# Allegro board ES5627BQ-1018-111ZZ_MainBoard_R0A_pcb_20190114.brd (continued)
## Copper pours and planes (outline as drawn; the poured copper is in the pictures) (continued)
XFP_3V3-R_P18 on BOTTOM (solid shape): 151.2,64.07 151.16,63.99 150.52,63.81 150.27,63.28 150.27,63.06 149.49,63.06 149.17,63.38 149.17,64.66 149.21,64.72 149.87,64.72 149.87,65.53 149.87,66.81 149.36,67.32 149.36,68.59 149.42,68.65 151.2,68.65
XFP_3V3-R_P19 on TOP (solid shape): 166.86,68.3 166.86,67.68 166.02,66.84 166.02,65.53 165.98,65.53 165.98,64.72 166.02,64.72 166.02,63.26 165.84,63.09 164.45,63.09 164.32,63.22 164.32,68.3 164.45,68.42 166.73,68.42
XFP_3V3-R_P20 on BOTTOM (solid shape): 163.71,63.44 163.65,63.38 163.65,63.13 163.58,63.06 163.38,63.06 163.38,63.42 163.06,63.75 162.34,63.82 162.12,63.13 162.12,63.12 162.12,63.06 161.99,63.06 161.68,63.38 161.68,64.66 161.72,64.71 162.38,64.71 162.38,65.53 162.38,66.81 161.87,67.32 161.87,68.59 161.93,68.65 163.71,68.65
XFP_3V3-R_P21 on TOP (solid shape): 179.5,68.3 179.5,67.53 178.76,66.8 178.73,66.8 178.73,65.98 178.73,65.98 178.73,65.53 178.64,65.53 178.64,64.71 178.73,64.71 178.73,63.34 178.48,63.09 177.08,63.09 176.96,63.22 176.96,68.3 177.08,68.42 179.37,68.42
XFP_3V3-R_P22 on BOTTOM (solid shape): 176.35,63.94 176.31,63.86 176.22,63.84 175.95,63.83 175.71,63.69 175.09,63.06 174.63,63.06 174.31,63.38 174.31,64.71 175.01,64.71 175.01,65.53 175.01,66.81 174.5,67.32 174.5,68.59 174.57,68.65 176.35,68.65
XFP_3V3-R_P23 on TOP (solid shape): 192.13,68.3 192.13,67.62 192.08,67.54 192.04,67.45 192.04,67.44 191.4,66.8 191.37,66.8 191.37,65.98 191.37,65.53 191.28,65.53 191.28,64.71 191.37,64.71 191.37,63.34 191.12,63.09 189.72,63.09 189.59,63.22 189.59,68.3 189.72,68.42 192,68.42
XFP_3V3-R_P24 on BOTTOM (solid shape): 188.98,63.91 188.94,63.83 188.85,63.82 188.22,63.73 187.92,63.16 187.89,63.09 187.82,63.06 187.27,63.06 186.95,63.38 186.95,64.55 187.08,64.68 187.54,64.68 187.58,64.71 187.65,64.71 187.65,65.53 187.65,65.53 187.65,66.81 187.14,67.32 187.14,68.55 187.24,68.55 187.3,68.62 187.36,68.62 187.4,68.65 188.98,68.65
XFP_3V3-T_P01 on TOP (solid shape): 31.52,68.3 31.52,63.22 31.39,63.09 29.74,63.09 29.49,63.34 29.49,64.61 29.59,64.71 30.21,64.71 30.21,64.74 30.25,64.74 30.25,66.77 29.67,67.35 29.69,67.39 29.75,67.64 29.69,67.89 29.69,68.2 29.62,68.28 29.62,68.3 29.74,68.42 31.39,68.42
XFP_3V3-T_P02 on BOTTOM (solid shape): 34.67,68.52 34.66,68.49 34.64,68.39 34.63,68.29 34.63,67.6 34.63,67.55 34.64,67.48 33.96,66.8 33.93,66.8 33.93,65.98 33.96,65.98 34.24,65.7 34.26,65.59 34.17,65.53 33.84,65.53 33.84,64.71 34.45,64.71 34.45,64.12 34.67,63.9 34.74,63.84 34.82,63.79 34.82,63.22 34.7,63.09 34.02,63.09 33.94,63.13 33.92,63.22 33.66,63.86 32.97,63.77 32.66,63.47 32.54,63.6 32.54,68.5 32.69,68.65 34.54,68.65
XFP_3V3-T_P03 on TOP (solid shape): 44.03,68.3 44.03,63.22 43.9,63.09 42.25,63.09 42,63.34 42,64.18 42,64.18 42.02,64.33 42,64.49 42,64.62 42.04,64.66 42.79,64.66 42.79,65.47 42.76,65.47 42.76,66.77 42.12,67.41 42.12,68.3 42.25,68.42 43.9,68.42
XFP_3V3-T_P04 on BOTTOM (solid shape): 47.18,68.52 47.17,68.49 47.15,68.39 47.14,68.29 47.14,67.6 47.14,67.55 47.15,67.48 46.47,66.8 46.44,66.8 46.44,65.98 46.47,65.98 46.75,65.7 46.77,65.59 46.68,65.53 46.35,65.53 46.35,64.71 46.96,64.71 46.96,64.12 47.18,63.9 47.25,63.84 47.33,63.79 47.33,63.22 47.2,63.09 45.67,63.09 45.62,63.14 45.62,63.35 45.45,63.75 45.05,63.92 45.05,68.5 45.2,68.65 47.05,68.65
XFP_3V3-T_P05 on TOP (solid shape): 56.6,68.3 56.6,63.22 56.48,63.09 54.82,63.09 54.57,63.34 54.57,64.59 54.58,64.59 54.58,64.62 54.68,64.72 55.36,64.72 55.36,65.53 55.33,65.53 55.33,66.77 54.72,67.39 54.7,67.46 54.7,68.3 54.82,68.42 56.48,68.42
XFP_3V3-T_P06 on BOTTOM (solid shape): 59.75,68.52 59.75,68.49 59.72,68.39 59.71,68.29 59.71,67.47 59.04,66.8 59.02,66.8 59.02,65.98 59.04,65.98 59.32,65.7 59.35,65.59 59.25,65.53 58.93,65.53 58.93,64.71 59.53,64.71 59.53,64.12 59.75,63.9 59.83,63.84 59.9,63.79 59.9,63.22 59.78,63.09 58.43,63.09 58.04,63.48 58.03,63.49 57.89,63.73 57.65,63.88 57.62,63.89 57.62,68.5 57.77,68.65 59.63,68.65
XFP_3V3-T_P07 on TOP (solid shape): 69.11,68.3 69.11,63.22 68.99,63.09 67.33,63.09 67.08,63.34 67.08,63.98 67.13,64.03 67.13,64.59 67.15,64.59 67.15,64.68 67.19,64.72 67.93,64.72 67.93,65.53 67.84,65.53 67.84,66.77 67.21,67.41 67.21,68.3 67.33,68.42 68.99,68.42
XFP_3V3-T_P08 on BOTTOM (solid shape): 72.26,68.52 72.25,68.49 72.23,68.39 72.22,68.29 72.22,67.6 72.22,67.55 72.23,67.48 71.55,66.8 71.52,66.8 71.52,65.98 71.55,65.98 71.83,65.7 71.86,65.59 71.76,65.53 71.44,65.53 71.44,64.71 72.04,64.71 72.04,64.12 72.26,63.9 72.33,63.84 72.41,63.79 72.41,63.22 72.29,63.09 70.92,63.09 70.85,63.12 70.47,63.5 70.47,63.51 70.34,63.69 70.16,63.81 70.13,63.82 70.13,68.5 70.28,68.65 72.13,68.65
XFP_3V3-T_P09 on TOP (solid shape): 81.62,68.58 81.62,63.22 81.49,63.09 79.84,63.09 79.59,63.34 79.59,64.61 79.69,64.71 80.31,64.71 80.31,64.74 80.35,64.74 80.35,66.77 79.72,67.41 79.72,68.51 79.84,68.64 81.56,68.64
XFP_3V3-T_P10 on BOTTOM (solid shape): 84.48,68.54 84.48,67.48 84.03,67.03 84.03,67.02 83.91,66.89 83.91,65.6 83.87,65.55 83.87,64.71 83.97,64.61 84.49,64.61 84.49,64.19 84.77,63.9 84.84,63.84 84.92,63.79 84.92,63.22 84.8,63.09 83.64,63.09 82.98,63.75 82.84,63.85 82.68,63.91 82.64,63.92 82.64,68.5 82.79,68.65 84.37,68.65
XFP_3V3-T_P11 on TOP (solid shape): 112.44,68.3 112.44,63.22 112.31,63.09 110.66,63.09 110.41,63.34 110.41,64.61 110.51,64.71 111.13,64.71 111.13,64.74 111.17,64.74 111.17,66.77 110.53,67.41 110.53,68.3 110.66,68.42 112.31,68.42
XFP_3V3-T_P12 on BOTTOM (solid shape): 115.59,68.52 115.58,68.49 115.56,68.39 115.55,68.29 115.55,68.15 115.44,68.03 115.29,67.81 115.23,67.54 115.23,67.5 115.25,67.35 115.29,67.21 114.88,66.8 114.85,66.8 114.85,65.97 114.8,65.92 114.8,65.53 114.76,65.53 114.76,64.71 115.37,64.71 115.37,64.12 115.59,63.9 115.66,63.84 115.74,63.79 115.74,63.22 115.62,63.09 115.59,63.09 114.09,63.09 114.09,63.26 113.92,63.71 113.5,63.95 113.46,63.95 113.46,68.5 113.61,68.65 115.46,68.65
XFP_3V3-T_P13 on TOP (solid shape): 125.01,68.3 125.01,63.22 124.89,63.09 123.23,63.09 122.98,63.34 122.98,64.61 123.08,64.71 123.7,64.71 123.7,64.74 123.74,64.74 123.74,66.77 123.11,67.41 123.11,68.3 123.23,68.42 124.89,68.42
XFP_3V3-T_P14 on BOTTOM (solid shape): 128.16,68.52 128.15,68.49 128.13,68.39 128.12,68.29 128.12,67.6 128.12,67.55 128.13,67.48 127.45,66.8 127.42,66.8 127.42,65.98 127.45,65.98 127.73,65.7 127.76,65.59 127.66,65.53 127.34,65.53 127.34,65.41 127.33,65.4 127.33,64.77 127.34,64.77 127.34,64.71 127.39,64.71 127.4,64.71 127.94,64.71 127.94,64.12 128.16,63.9 128.23,63.84 128.31,63.79 128.31,63.22 128.19,63.09 126.58,63.09 126.58,63.35 126.44,63.77 126.07,64.02 126.03,64.03 126.03,68.5 126.18,68.65 128.03,68.65
XFP_3V3-T_P15 on TOP (solid shape): 133.15,68.17 133.15,63.09 133.02,62.97 131.37,62.97 131.12,63.22 131.12,64.49 131.22,64.59 131.84,64.59 131.84,64.62 131.88,64.62 131.88,65.26 131.99,65.37 131.99,66.78 131.42,67.35 131.42,68.3 133.02,68.3
XFP_3V3-T_P16 on BOTTOM (solid shape): 136.3,68.4 136.29,68.37 136.27,68.27 136.26,68.16 136.26,67.48 136.26,67.43 136.27,67.36 135.59,66.68 135.56,66.68 135.56,65.86 135.59,65.86 135.87,65.58 135.89,65.47 135.8,65.41 135.47,65.41 135.47,64.59 136.08,64.59 136.08,64 136.3,63.78 136.37,63.72 136.45,63.67 136.45,63.09 136.33,62.97 135.02,62.97 134.39,63.6 134.3,63.67 134.2,63.72 134.17,63.73 134.17,68.38 134.32,68.53 136.17,68.53
XFP_3V3-T_P17 on TOP (solid shape): 151.17,68.3 151.17,63.22 151.05,63.09 149.4,63.09 149.14,63.34 149.14,64.61 149.25,64.72 149.87,64.72 149.87,64.74 149.9,64.74 149.9,66.77 149.27,67.41 149.27,68.3 149.4,68.42 151.05,68.42
XFP_3V3-T_P18 on BOTTOM (solid shape): 154.33,68.52 154.32,68.49 154.29,68.24 154.35,67.99 154.35,67.53 153.61,66.8 153.59,66.8 153.59,66.77 153.51,66.69 153.51,65.53 153.5,65.53 153.5,64.71 153.51,64.71 153.51,64.68 153.69,64.49 154.1,64.49 154.1,64.12 154.32,63.9 154.4,63.84 154.48,63.79 154.48,63.22 154.35,63.09 153.42,63.09 152.61,63.9 152.43,64.03 152.23,64.1 152.19,64.1 152.19,68.5 152.34,68.65 154.2,68.65
XFP_3V3-T_P19 on TOP (solid shape): 163.68,68.3 163.68,63.22 163.56,63.09 161.91,63.09 161.65,63.34 161.65,64.61 161.76,64.72 162.38,64.72 162.38,64.74 162.41,64.74 162.41,66.77 161.78,67.41 161.78,68.3 161.91,68.42 163.56,68.42
XFP_3V3-T_P20 on BOTTOM (solid shape): 166.84,68.52 166.83,68.49 166.8,68.39 166.79,68.29 166.79,67.73 166.02,66.95 166.02,65.89 166.2,65.7 166.22,65.59 166.13,65.53 165.98,65.53 165.98,64.72 166.53,64.72 166.53,64.12 166.79,63.86 166.88,63.78 166.99,63.72 166.99,63.22 166.86,63.09 165.21,63.09 165.13,63.17 165.13,63.35 165.02,63.68 164.73,63.89 164.7,63.9 164.7,68.5 164.85,68.65 166.71,68.65
XFP_3V3-T_P21 on TOP (solid shape): 176.32,68.3 176.32,63.22 176.19,63.09 174.54,63.09 174.29,63.34 174.29,64.61 174.39,64.71 175.01,64.71 175.01,64.74 175.05,64.74 175.05,66.77 174.42,67.41 174.42,68.3 174.54,68.42 176.19,68.42
XFP_3V3-T_P22 on BOTTOM (solid shape): 179.47,68.52 179.46,68.49 179.44,68.39 179.43,68.29 179.43,67.47 178.76,66.8 178.73,66.8 178.73,65.98 178.76,65.98 179.04,65.7 179.06,65.59 178.97,65.53 178.64,65.53 178.64,64.71 179.25,64.71 179.25,64.12 179.47,63.9 179.54,63.84 179.62,63.79 179.62,63.22 179.5,63.09 178.2,63.09 177.6,63.69 177.49,63.77 177.37,63.83 177.34,63.84 177.34,68.5 177.49,68.65 179.34,68.65
XFP_3V3-T_P23 on TOP (solid shape): 188.96,68.3 188.96,63.22 188.95,63.21 188.95,62.91 188.75,62.71 187.56,62.71 186.92,63.34 186.92,64.61 187.03,64.71 187.65,64.71 187.65,64.74 187.69,64.74 187.69,66.77 187.05,67.41 187.05,68.3 187.18,68.42 188.83,68.42
XFP_3V3-T_P24 on BOTTOM (solid shape): 192.11,68.52 192.1,68.49 192.08,68.39 192.07,68.29 192.07,67.79 191.9,67.55 191.85,67.27 191.85,67.25 191.4,66.8 191.37,66.8 191.37,65.98 191.4,65.98 191.68,65.7 191.7,65.59 191.61,65.53 191.28,65.53 191.28,64.71 191.89,64.71 191.89,64.12 192.11,63.9 192.18,63.84 192.26,63.79 192.26,63.22 192.13,63.09 191.2,63.09 191.07,63.19 190.92,63.25 190.91,63.26 190.32,63.84 190.18,63.95 190.01,64.02 189.97,64.03 189.97,68.5 190.13,68.65 191.98,68.65
XFP_3V3_12V_VIN on TOP: 173.5,106.7 169.44,106.7 169.31,106.83 169.31,107.59 169.19,107.72 163.47,107.72 162.46,106.7 158.01,106.7 157.88,106.83 157.88,107.46 156.79,108.56 156.79,109.14 156.89,109.24 157.5,109.24 157.55,109.29 157.55,109.93 158.01,110.39 166.52,110.39 166.65,110.51 172.23,110.51 172.36,110.39 172.36,109.37 172.49,109.24 173.5,109.24 173.63,109.12 173.63,106.83
XFP_3V3_12V_VIN on BOTTOM: 157.96,110.36 171.27,110.36 171.95,109.67 171.95,106.98 171.68,106.7 157.71,106.7 157.17,107.24 157.17,109.57
XFP_3V3_GND on TOP: 147.22,90.45 147.09,90.57 147.09,92.1 147.34,92.35 147.72,92.35 148.1,92.73 149.12,92.73 149.25,92.61 149.25,89.31 149.04,89.1 148,89.1 147.22,89.88
XFP_3V3_GND on TOP: 143.59,102.55 143.59,101.3 143.61,101.3 143.88,101.03 145.44,101.03 145.75,101.34 145.75,102.7 145.62,102.83 143.87,102.83
XFP_3V3_GND on S7: 143.91,100.15 143.66,100.4 143.66,101.62 143.82,101.79 145.4,101.79 147.98,99.21 147.98,96.29 148.3,95.97 148.3,93.88 148.99,93.18 148.99,91.74 149.64,91.1 150.53,91.1 151.22,91.8 151.22,93.21 150.53,93.9 150.53,95.84 151.03,96.34 152.75,96.34 153.44,95.65 153.44,91.59 150.7,88.85 145.18,88.85 143.91,90.11
XFP_3V3_P01_02 on TOP (solid shape): 35.71,73.12 35.71,69.69 35.61,69.59 34.92,69.59 34.92,69.06 32.02,69.06 31.66,69.06 29.49,69.06 29.36,69.18 29.36,69.44 29.26,69.54 29.26,69.72 28.6,69.72 28.6,70.33 28.92,70.65 28.94,70.65 29.15,70.71 29.31,70.84 32.03,70.84 32.28,71.09 32.28,73.25 32.54,73.5 35.33,73.5
XFP_3V3_P01_02 on BOTTOM (solid shape): 35.71,72.84 35.71,69.85 35.51,69.64 35.1,69.64 35.05,69.59 34.92,69.59 34.92,69.36 34.85,69.29 32.43,69.29 29.69,69.29 29.59,69.39 29.59,69.46 29.49,69.57 29.26,69.57 29.26,69.72 28.6,69.72 28.6,70.33 28.92,70.65 28.94,70.65 29.15,70.71 29.31,70.84 32.03,70.84 32.28,71.09 32.28,72.11 33.43,73.25 35.3,73.25
XFP_3V3_P03_04 on TOP (solid shape): 48.22,73.12 48.22,69.69 48.12,69.59 47.43,69.59 47.43,69.06 44.53,69.06 44.17,69.06 42,69.06 41.87,69.18 41.87,69.44 41.77,69.54 41.77,69.72 41.11,69.72 41.11,70.33 41.5,70.72 41.52,70.73 41.66,70.76 41.78,70.84 42.79,70.84 43.21,70.62 43.64,70.84 46.03,70.84 46.25,71.06 46.25,73.36 46.4,73.5 47.84,73.5
XFP_3V3_P03_04 on BOTTOM (solid shape): 48.22,72.84 48.22,69.85 48.02,69.64 47.61,69.64 47.56,69.59 47.43,69.59 47.43,69.36 47.36,69.29 47.29,69.29 44.94,69.29 44.93,69.29 42.2,69.29 42.1,69.39 42.1,69.46 42,69.57 41.77,69.57 41.77,69.72 41.11,69.72 41.11,70.33 41.5,70.72 41.52,70.73 41.66,70.76 41.78,70.84 42.79,70.84 43.21,70.62 43.64,70.84 44.54,70.84 44.79,71.09 44.79,72.11 45.93,73.25 47.81,73.25
XFP_3V3_P05_06 on TOP (solid shape): 60.79,73.12 60.79,69.69 60.69,69.59 60.01,69.59 60.01,69.06 57.1,69.06 56.74,69.06 54.57,69.06 54.44,69.18 54.44,69.44 54.34,69.54 54.34,69.72 53.68,69.72 53.68,70.33 54.19,70.84 55.15,70.84 55.24,70.75 55.68,70.75 56.05,70.66 56.38,70.84 57.11,70.84 57.11,70.84 58.49,70.84 58.82,71.17 58.82,73.36 58.96,73.5 60.41,73.5
XFP_3V3_P05_06 on BOTTOM (solid shape): 61.18,72.46 61.18,70.23 60.59,69.64 60.18,69.64 60.13,69.59 60.01,69.59 60.01,69.36 59.93,69.29 57.51,69.29 54.77,69.29 54.67,69.39 54.67,69.46 54.57,69.57 54.34,69.57 54.34,69.72 53.68,69.72 53.68,70.33 54.19,70.84 55.58,70.84 55.98,70.66 56.38,70.84 57.11,70.84 57.36,71.09 57.36,72.11 58.51,73.25 60.39,73.25
XFP_3V3_P07_08 on TOP (solid shape): 73.3,73.12 73.3,69.69 73.2,69.59 72.52,69.59 72.52,69.06 69.61,69.06 69.25,69.06 67.08,69.06 66.95,69.18 66.95,69.44 66.85,69.54 66.85,69.72 66.19,69.72 66.19,70.33 66.39,70.53 66.43,70.51 66.64,70.43 66.87,70.44 66.88,70.45 67.02,70.45 67.41,70.84 67.57,70.84 67.97,70.44 68.09,70.44 68.1,70.43 68.51,70.48 68.77,70.8 68.78,70.84 70.86,70.84 71.28,71.25 71.28,73.38 71.4,73.5 72.92,73.5
XFP_3V3_P07_08 on BOTTOM (solid shape): 73.3,72.84 73.3,69.85 73.1,69.64 72.69,69.64 72.64,69.59 72.52,69.59 72.52,69.36 72.44,69.29 70.02,69.29 67.28,69.29 67.18,69.39 67.18,69.46 67.08,69.57 66.85,69.57 66.85,69.72 66.19,69.72 66.19,70.33 66.39,70.53 66.43,70.51 66.9,70.45 67.23,70.8 67.24,70.84 67.73,70.84 67.74,70.8 68.25,70.41 68.77,70.8 68.78,70.84 69.62,70.84 69.87,71.09 69.87,72.11 71.02,73.25 72.9,73.25
XFP_3V3_P09_10 on TOP (solid shape): 85.33,72.52 85.33,72.46 85.34,72.33 85.32,72.33 85.32,70.38 85.54,70.38 85.54,70.09 85.61,70.03 85.6,70 85.61,69.85 85.66,69.71 85.65,69.61 85.56,69.57 85.12,69.57 85.08,69.53 85.03,69.53 85.03,69.06 84.93,69.06 84.73,69.26 84.7,69.26 84.68,69.28 82.25,69.28 82.23,69.26 81.84,69.26 81.82,69.27 79.63,69.27 79.46,69.44 79.46,69.57 79.4,69.63 79.36,69.63 79.36,69.72 78.7,69.72 78.7,70.33 78.85,70.47 82.91,70.47 83.32,70.89 83.32,73 83.82,73.5 85.33,73.5
XFP_3V3_P09_10 on BOTTOM (solid shape): 85.31,73 85.31,72.21 85.68,71.84 85.56,71.72 85.56,69.95 85.59,69.77 85.67,69.61 85.7,69.58 85.65,69.53 85.03,69.53 85.03,69.37 84.95,69.29 84.64,69.29 82.53,69.29 82.53,69.29 79.79,69.29 79.79,69.58 79.68,69.7 79.36,69.7 79.36,69.72 78.74,69.72 78.7,69.75 78.7,70.33 79.02,70.65 79.84,70.65 80.03,70.84 80.35,70.84 80.83,70.54 81.31,70.84 82.13,70.84 82.38,71.09 82.38,72.11 83.53,73.25 85.06,73.25
XFP_3V3_P11_12 on TOP (solid shape): 116.63,73.12 116.63,69.69 116.54,69.6 115.96,69.6 115.95,69.59 115.84,69.59 115.84,69.09 115.81,69.06 112.94,69.06 112.58,69.06 110.41,69.06 110.31,69.15 110.31,69.7 110.24,69.76 109.61,69.76 109.52,69.86 109.52,70.33 109.91,70.72 109.93,70.73 110.05,70.75 110.16,70.81 110.68,70.81 110.71,70.84 112.95,70.84 113.2,71.09 113.2,73.25 113.46,73.5 116.25,73.5
XFP_3V3_P11_12 on BOTTOM (solid shape): 116.63,72.84 116.63,69.85 116.43,69.64 116.02,69.64 115.97,69.59 115.84,69.59 115.84,69.36 115.77,69.29 113.34,69.29 110.61,69.29 110.51,69.39 110.51,69.46 110.25,69.73 109.63,69.73 109.52,69.84 109.52,70.33 109.91,70.72 109.93,70.73 110.07,70.76 110.19,70.84 112.95,70.84 113.2,71.09 113.2,72.11 114.34,73.25 116.22,73.25
XFP_3V3_P13_14 on TOP (solid shape): 129.2,73.12 129.2,69.69 129.13,69.62 128.42,69.62 128.36,69.57 128.36,69.12 128.3,69.06 125.51,69.06 122.98,69.06 122.9,69.14 122.9,69.5 122.77,69.63 122.75,69.63 122.75,69.72 122.09,69.72 122.09,70.33 122.49,70.72 122.5,70.73 122.62,70.75 122.73,70.81 123.25,70.81 123.28,70.84 125.52,70.84 125.77,71.09 125.77,73.25 126.03,73.5 128.82,73.5
XFP_3V3_P13_14 on BOTTOM (solid shape): 129.2,72.84 129.2,69.85 129,69.64 128.59,69.64 128.54,69.59 128.42,69.59 128.42,69.36 128.34,69.29 128.28,69.29 125.92,69.29 125.92,69.29 123.18,69.29 123.16,69.31 123.16,69.5 122.96,69.7 122.75,69.7 122.75,69.72 122.13,69.72 122.09,69.76 122.09,70.66 122.2,70.77 122.23,70.76 122.51,70.73 122.76,70.84 125.52,70.84 125.77,71.09 125.77,72.11 126.92,73.25 128.8,73.25
XFP_3V3_P15_16 on TOP (solid shape): 137.34,73 137.34,69.57 137.3,69.52 136.57,69.52 136.49,69.44 136.49,69.06 136.36,68.94 131.12,68.94 130.99,69.06 130.99,69.47 130.86,69.6 130.23,69.6 130.23,70.21 130.5,70.48 134.16,70.48 135.03,71.35 135.03,73 135.41,73.38 136.96,73.38
XFP_3V3_P15_16 on BOTTOM (solid shape): 137.34,72.72 137.34,69.72 137.14,69.52 136.73,69.52 136.68,69.47 136.55,69.47 136.55,69.24 136.48,69.16 134.06,69.16 131.54,69.16 131.07,69.63 130.29,69.63 130.23,69.7 130.23,70.21 130.74,70.71 132,70.71 132.37,70.56 132.74,70.71 133.66,70.71 133.91,70.97 133.91,71.98 135.06,73.13 136.93,73.13
XFP_3V3_P17_18 on TOP (solid shape): 155.37,73.12 155.37,69.69 155.26,69.59 154.58,69.59 154.58,69.57 154.5,69.57 154.5,69.06 151.67,69.06 149.14,69.06 149.02,69.18 149.02,69.44 148.91,69.54 148.91,69.72 148.25,69.72 148.25,70.33 148.76,70.84 151.68,70.84 151.94,71.09 151.94,73.25 152.19,73.5 154.98,73.5
XFP_3V3_P17_18 on BOTTOM (solid shape): 155.37,72.84 155.37,69.85 155.16,69.64 154.76,69.64 154.71,69.59 154.58,69.59 154.58,69.36 154.5,69.29 154.44,69.29 152.08,69.29 152.08,69.29 149.35,69.29 149.24,69.39 149.24,69.46 149.14,69.57 148.91,69.57 148.91,69.72 148.25,69.72 148.25,70.33 148.76,70.84 151.68,70.84 151.94,71.09 151.94,72.11 153.08,73.25 154.96,73.25
XFP_3V3_P19_20 on TOP (solid shape): 167.87,73.12 167.87,69.69 167.77,69.59 167.09,69.59 167.09,69.06 166.99,69.06 164.18,69.06 163.82,69.06 161.65,69.06 161.52,69.18 161.52,69.44 161.42,69.54 161.42,69.72 161.24,69.72 161.24,69.73 160.76,69.73 160.76,70.33 161.27,70.84 164.19,70.84 164.45,71.09 164.45,73.25 164.7,73.5 167.49,73.5
XFP_3V3_P19_20 on BOTTOM (solid shape): 167.87,72.84 167.87,69.85 167.67,69.64 167.27,69.64 167.21,69.59 167.09,69.59 167.09,69.36 167.01,69.29 164.59,69.29 161.85,69.29 161.75,69.39 161.75,69.46 161.65,69.57 161.42,69.57 161.42,69.72 160.76,69.72 160.76,70.33 161.27,70.84 164.19,70.84 164.45,71.09 164.45,72.11 165.59,73.25 167.47,73.25
XFP_3V3_P21_22 on TOP (solid shape): 180.51,73.12 180.51,69.69 180.41,69.59 179.72,69.59 179.72,69.57 179.71,69.57 179.71,69.06 176.82,69.06 174.29,69.06 174.16,69.18 174.16,69.44 174.06,69.54 174.06,69.72 173.88,69.72 173.88,69.72 173.4,69.72 173.4,70.33 173.91,70.84 176.83,70.84 177.08,71.09 177.08,73.25 177.34,73.5 180.13,73.5
XFP_3V3_P21_22 on BOTTOM (solid shape): 180.51,72.84 180.51,69.85 180.31,69.64 179.9,69.64 179.85,69.59 179.72,69.59 179.72,69.36 179.65,69.29 179.58,69.29 177.23,69.29 177.22,69.29 174.49,69.29 174.46,69.31 174.21,69.31 174.06,69.46 174.06,69.72 173.42,69.72 173.4,69.74 173.4,70.33 173.91,70.84 176.83,70.84 177.08,71.09 177.08,72.11 178.23,73.25 180.1,73.25
XFP_3V3_P23_24 on TOP (solid shape): 193.15,73.12 193.15,69.69 193.08,69.62 192.49,69.62 192.46,69.59 192.36,69.59 192.36,69.06 189.46,69.06 189.09,69.06 186.92,69.06 186.8,69.18 186.8,69.44 186.7,69.54 186.7,69.72 186.04,69.72 186.04,70.33 186.52,70.81 187.2,70.81 187.22,70.84 189.46,70.84 189.72,71.09 189.72,72.82 190.4,73.5 192.77,73.5
XFP_3V3_P23_24 on BOTTOM (solid shape): 193.15,72.84 193.15,69.85 192.94,69.64 192.54,69.64 192.49,69.59 192.36,69.59 192.36,69.36 192.28,69.29 189.86,69.29 187.14,69.29 187.1,69.25 187.04,69.25 186.97,69.19 186.85,69.19 186.72,69.31 186.72,69.63 186.7,69.65 186.7,69.72 186.08,69.72 186.04,69.76 186.04,70.33 186.54,70.84 189.46,70.84 189.72,71.09 189.72,72.95 190.02,73.25 192.74,73.25
XFP_3V3_PCL_SW on TOP (solid shape): 157.75,103.15 162.46,103.15 162.72,103.4 163.72,103.4 163.84,103.27 163.95,103.27 163.95,103.12 165.28,103.12 165.28,103.15 165.48,103.15 165.48,103.12 166.8,103.12 166.8,103.15 167.91,103.15 168.05,103.28 168.49,103.32 171.82,103.32 172.22,102.92 172.22,98.08 171.83,97.69 158.14,97.69 157.76,98.07 157.76,98.84 157.89,99.36 157.5,99.73 157.49,99.73 157.15,100.07 157.15,100.38 156.84,100.38 156.61,100.61 156.61,103.27 156.74,103.4 157.49,103.4
N61195405 on TOP: 204.57,252.81 204.57,247.22 205.16,246.63 209.04,246.63 209.27,246.41 214.2,246.41 214.25,246.46 214.25,247.04 214.1,247.19 210.49,247.19 209.58,248.11 209.58,252.78 208.74,253.62 205.38,253.62
N61307888 on G2 (solid shape): outline of 1081 points within 250.38,12.67 265.97,70.94
N61307888 on V3 (solid shape): outline of 1081 points within 250.38,12.67 265.97,70.94
N61307888 on G4 (solid shape): outline of 1081 points within 250.38,12.67 265.97,70.94
N61307888 on G6 (solid shape): outline of 1081 points within 250.38,12.67 265.97,70.94
N61307888 on G8 (solid shape): outline of 1081 points within 250.38,12.67 265.97,70.94
N61307888 on G10 (solid shape): outline of 1081 points within 250.38,12.67 265.97,70.94
N61307888 on G11 (solid shape): outline of 1081 points within 250.38,12.67 265.97,70.94
N61307888 on G13 (solid shape): outline of 1081 points within 250.38,12.67 265.97,70.94
N61307888 on G15 (solid shape): outline of 1081 points within 250.38,12.67 265.97,70.94
N61307888 on G17 (solid shape): outline of 1081 points within 250.38,12.67 265.97,70.94
N61307888 on G19 (solid shape): outline of 1115 points within 250.38,12.67 265.97,70.94
N61983825 on G2 (solid shape): outline of 1159 points within 220.44,12.8 240.41,80.36
N61983825 on G4 (solid shape): outline of 1159 points within 220.44,12.8 240.41,80.36
N61983825 on G6 (solid shape): outline of 1159 points within 220.44,12.8 240.41,80.36
N61983825 on G8 (solid shape): outline of 1160 points within 220.44,12.8 240.43,80.36
N61983825 on G10 (solid shape): outline of 1160 points within 220.44,12.8 240.43,80.36
N61983825 on G11 (solid shape): outline of 1160 points within 220.44,12.8 240.43,80.36
N61983825 on G13 (solid shape): outline of 1160 points within 220.44,12.8 240.43,80.36
N61983825 on G15 (solid shape): outline of 1160 points within 220.44,12.8 240.43,80.36
N61983825 on G17 (solid shape): outline of 1170 points within 220.44,12.8 240.43,80.36
N61983825 on G19 (solid shape): outline of 1201 points within 220.44,12.8 240.43,80.36

Small or netless copper shapes (teardrops, artwork), in the pictures only: 44 on TOP, 1 on BOTTOM, 1 on V3, 2 on S5, 2 on S7, 1 on S9, 1 on S12, 1 on S14, 2 on S16, 1 on G10, 2 on V18

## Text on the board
Ref Des/Silkscreen Bottom: A | B | G | W
User.Comments: CR_CONN_POWER_1 | CR_UNNAMED_1 | CR_UNNAMED_25 | CR_1_9 | CR_CONN_POWER_2 | CR_UNNAMED_2 | CR_UNNAMED_26 | CR_0_2 | CR_1_10 | CR_CONN_POWER_3 | CR_UNNAMED_27 | CR_1_11 | CR_UNNAMED_3 | CR_2_3 | CR_0_4 | CR_UNNAMED_28 | CR_CONN_POWER_4 | CR_UNNAMED_4 | CR_1_13 | CR_2_1 | CR_CONN_POWER_5 | CR_UNNAMED_29 | CR_1_14 | CR_2_2 | CR_UNNAMED_30 | CR_CONN_POWER_10 | CR_2_4 | CR_CONN_POWER_9 | CR_UNNAMED_6 | CR_UNNAMED_7 | CR_1_15 | CR_UNNAMED_8 | CR_1_16 | CR_2_5 | CR_CONN_POWER_7 | CR_UNNAMED_9 | CR_1_17 | CR_2_6 | CR_CONN_POWER_8 | CR_UNNAMED_10 | CR_U160_3 | CR_CONN18_1 | CR_CONN18_2 | CR_U160_6 | CR_U25_1 | CR_U25_2 | CR_2_7 | CR_1_18 | CR_CONN_POWER_11 | CR_UNNAMED_11 | CR_UNNAMED_34 | CR_2_8 | CR_CONN_POWER_12 | CR_1_19 | CR_UNNAMED_35 | CR_UNNAMED_12 | CR_2_9 | CR_1_20 | CR_CONN_POWER_13 | CR_UNNAMED_36 | CR_UNNAMED_13 | CR_2_10 | CR_CONN_POWER_14 | CR_UNNAMED_37 | CR_1_21 | CR_UNNAMED_14 | CR_2_11 | CR_CONN_POWER_15 | CR_UNNAMED_38 | CR_UNNAMED_15 | CR_2_12 | CR_CONN_POWER_16 | CR_UNNAMED_39 | CR_UNNAMED_16 | CR_2_13 | CR_UNNAMED_40 | CR_CONN_POWER_17 | CR_UNNAMED_17 | CR_2_14 | CR_UNNAMED_41 | CR_CONN_POWER_18 | CR_UNNAMED_18 | CR_2_15 | CR_UNNAMED_42 | CR_CONN_POWER_19 | CR_UNNAMED_19 | CR_2_16 | CR_CONN_POWER_20 | CR_UNNAMED_20
Ref Des/Assembly Top: 37 | 36 | 35 | 34 | 33 | 32 | 31 | 30 | 29 | P/N:142000002193H REV.0A
Ref Des/Silkscreen Top: RR | U | K | P | D | T | WW | B | C | Q | PO | UU | EE | A | 0 | O
User.10: ∅4.2 [∅0.165] | {\Fromans,stsl|c134;4-∅4.5 [∅0.177]}
User.11: TOP (COMPONENT_SIDE)                       1
User.12: G2 (GND_LAYER_2)                           2
User.13: S5 (SIGNAL_LAYER_5)                           5
User.14: BOT (SOLDER_SIDE)                         20
User.15: SST (SILKSCREEN_TOP)                      21
User.16: SSB (SILKSCREEN_BOTTOM)                   22
User.17: SMT (SOLDER_MASK_TOP)                     23
User.18: SMB (SOLDER_MASK_BOTTOM)                  24
User.19: DRILL(FINISH HOLE SIZE LIST)                  27 | First drill hole + secind drill hole=8 | Visible drill hole=4 | Drill size=177 mil
User.20: PMT (PASTE_MASK_TOP)                     25
User.21: PMB (PASTE_MASK_BOTTOM)                  26
User.22: DIM (BOARD_DIMENSION)                    34
User.24: G4 (GND_LAYER_4 )                         4
User.25: G6 (GND_LAYER_6)                           6
User.26: S7 (SIGNAL_LAYER_7)                           7
User.27: G8 (VCC_LAYER_8)                           8
User.30: G11 (GND_LAYER_11)                         11
User.31: S12 (SIGNAL_LAYER_12)                         12
User.32: G13 (GND_LAYER_13)                         13
User.33: G15 (GND_LAYER_15)                         15
User.34: S14 (SIGNAL_LAYER_14)                         14
User.35: G17 (GND_LAYER_17)                         17
User.36: S16 (SIGNAL_LAYER_16)                         16
User.37: BACKDRILL(DRILL-BD-20-17)                  33 | NO MUST CUT LAYER:S16 | MUST CUT LAYER:G17
User.38: BACKDRILL(DRILL-BD-20-15)                   28 | NO MUST CUT LAYER:S14 | MUST CUT LAYER:G15
User.39: BACKDRILL(DRILL-BD-20-13)                   32 | NO MUST CUT LAYER:S12 | MUST CUT LAYER:G13
User.40: BACKDRILL(DRILL-BD-20-10)                  30 | NO MUST CUT LAYER:S9 | MUST CUT LAYER:G10
User.41: BACKDRILL(DRILL-BD-20-6)                     28 | NO MUST CUT LAYER:S5 | MUST CUT LAYER:G6
User.42: BACKDRILL(DRILL-BD-20-8)                     29 | NO MUST CUT LAYER:S7 | MUST CUT LAYER:G8
User.43: V18 (VCC_LAYER_18)                    18
User.44: V3 (VCC_LAYER_3)                          3
User.45: 9 | 8 | 7 | 3 | 2 | 1 | H | F | D | B | T | P | M | K | N | J | G | C | A | R | L | E | RB134 | RB135 | CB322 | RB1210 | CB922 | R1195 | R1044 | R1054 | R1045 | R1039 | CB1078 | CB321 | RB1200 | LEDB6 | CB323 | CB1076 | RB184 | CB1030 | TP50 | LEDB5 | RB186 | CB1015 | CB1066 | CB1064 | CB1005 | CB1004 | CB1003 | CB1016 | CB996 | CB1072 | CB1070 | RB1199 | CB1006 | CB1033 | CB1013 | CB1001 | CB1007 | CB1008 | CB1058 | CB1036 | CB1022 | CB1024 | R1116 | R1098 | RB1212 | RB256 | R1100 | R1082 | TP51 | RB1215 | RB1206 | RB1208 | R1084 | R1086 | RB760 | RB1209 | LEDB4 | CB1088 | RB325 | RB1213 | CB440 | LEDB3 | UB71 | CB942 | CB950 | CB953 | CB954 | RB324 | FB3 | CB329 | RB662 | RB669 | RB678 | RB688 | RB273 | RB278 | RB280 | RB283 | R1237 | RB1217 | RB766 | CB896 | R332 | CB736 | CB1041 | CB1044 | UB10 | RB1216 | CB710 | RB223 | CB895 | CB1080 | CB737 | R1236 | UB70 | CB1083 | CB1085 | CB1079 | CB1082 | RB1201 | RB639 | CB755 | R1110 | CB894 | C538 | CB1040 | CB1042 | RB1221 | RB1219 | CB795 | TPB54 | RB155 | RB748 | CB730 | CB687 | CB711 | RB638 | CB939 | CB893 | CB794 | CB668 | TPB55 | RB750 | CB383 | CB584 | CB1039 | R1115 | R1114 | R1096 | R1097 | R1102 | R1103 | CB1043 | CB1073 | CB940 | RB203 | RB747 | R182 | R1081 | CB1054 | RB1211 | CB1037 | CB1050 | CB785 | LB72 | RB452 | RB488 | RB524 | RB560 | RB762 | RB763 | RB451 | RB487 | RB523 | RB201 | RB188 | RB561 | RB489 | RB152 | RB161 | RB525 | RB164 | RB166 | RB170 | RB453 | RB211 | CB522 | RB225 | RB217 | RB151 | CB351 | RB160 | RB163 | RB230 | RB165 | RB169 | CB881 | UB7 | RB216 | RB224 | RB226 | RB229 | RB231 | RB234 | CB849 | QB4 | DB6 | QB6 | R1228 | UB11 | CB880 | RB559 | CB848 | R1170 | R1171 | LB2 | CB11 | RB149 | CB349 | FB7 | RB558 | CB105 | DB3 | RB157 | CB97 | RB765 | RB557 | CB879 | CB847 | RB556 | CB934 | LB3 | CB878 | CB846 | RB555 | CB14 | CB925 | CB147 | CB1093 | RB450 | RB486 | RB522 | CB845 | UB2 | CB146 | CB877 | DB4 | RB554 | RB449 | RB485 | RB521 | CB844 | CB200 | CB178 | CB876 | CB96 | CB103 | RB448 | RB484 | RB520 | FB6 | QB5 | CB843 | RB553 | LB5 | QB7 | LB6 | RB44 | CB29 | CB875 | RB447 | RB483 | RB519 | RB576 | CB935 | CB225 | CB842 | RB446 | RB482 | RB518 | CB72 | CB400 | CB417 | CB240 | CB874 | RB575 | RB215 | RB445 | RB481 | RB517 | DB5 | CB109 | CB121 | CB129 | CB841 | RB574 | RB181 | RB504 | RB540 | RB468 | RB159 | RB538 | CB101 | CB873 | RB503 | RB467 | RB539 | RB189 | CB170 | RB502 | RB466 | CB108 | CB128 | CB840 | CB872 | RB4 | CB509 | RB465 | RB501 | RB537 | RB573 | UB14 | CB793 | CB239 | CB224 | RB572 | RB536 | RB500 | RB464 | QB2 | CB21 | CB839 | CB871 | RB109 | RB659 | RB571 | RB535 | RB123 | LB85 | RB499 | LB16 | RB463 | CB219 | CB245 | CB952 | CB272 | CB252 | RB97 | CB959 | RB686 | CB256 | CB194 | CB184 | CB171 | CB223 | CB237 | RB462 | CB870 | LB81 | LB79 | RB498 | RB570 | RB534 | RB87 | RB652 | RB93 | RB685 | RB569 | RB533 | RB497 | RB461 | CB958 | CB938 | RB496 | RB532 | RB568 | LB26 | RB183 | CB123 | RB460 | LB80 | CB545 | RB582 | CB330 | CB334 | CB328 | RB664 | RB673 | RB552 | RB516 | CB594 | CB837 | RB599 | RB608 | RB616 | RB629 | RB637 | CB869 | CB137 | CB158 | CB169 | CB179 | CB188 | CB207 | CB222 | CB238 | CB259 | RB444 | RB480 | RB581 | RB591 | RB648 | RB658 | RB663 | RB672 | DB7 | CB456 | CB570 | UB3 | CB89 | CB733 | LB11 | RB443 | RB479 | RB515 | RB551 | RB689 | RB697 | RB708 | RB714 | CB759 | RB727 | CB868 | CB836 | LB15 | RB442 | RB478 | RB550 | RB514 | CB215 | CB189 | CB500 | RB679 | RB703 | CB835 | CB867 | C447 | RB590 | RB647 | RB8 | RB657 | RB607 | RB628 | RB228 | CB973 | RB721 | CB985 | RB744 | RB513 | RB615 | RB598 | RB636 | CB283 | CB102 | CB111 | CB834 | CB866 | RB441 | RB549 | RB440 | RB476 | RB512 | RB548 | RB477 | CB163 | CB264 | CB151 | CB126 | CB949 | RB743 | RB746 | CB757 | SWB2 | CB654 | CB404 | RB176 | CB833 | LB22 | CB865 | UB12 | CB211 | RB218 | CB120 | RB742 | RB745 | RB89 | RB94 | RB439 | RB475 | RB511 | RB547 | RB546 | RB438 | RB474 | RB510 | UB17 | RB666 | CB205 | RB683 | CB686 | RB702 | RB614 | RB580 | RB589 | RB597 | RB38 | RB22 | RB635 | CB550 | CB290 | CB413 | CB366 | RB606 | RB627 | RB646 | RB707 | SWB1 | CB618 | CB832 | CB5 | RB5 | RB37 | RB21 | CB864 | RB694 | RB656 | RB677 | CB313 | RB47 | CB90 | CB212 | RB713 | CB32 | UB1 | RB46 | TPB47 | RB173 | RB712 | RB720 | CB315 | RB437 | RB473 | RB509 | RB545 | RB596 | RB676 | RB706 | CB9 | RB626 | RB655 | RB701 | RB588 | RB579 | RB645 | RB605 | RB613 | RB634 | CB696 | RB436 | RB472 | RB508 | RB544 | RB682 | RB693 | CB975 | RB665 | RB578 | RB654 | UB16 | OSCB1 | CB314 | RB595 | RB603 | RB612 | RB633 | RB435 | RB471 | RB507 | RB543 | RB731 | RB625 | RB644 | RB587 | CB279 | CB292 | CB236 | RB99 | RB85 | RB90 | RB40 | RB7 | CB110 | RB110 | RB116 | RB102 | RB730 | RB741 | CB857 | CB34 | RB6 | RB39 | CB210 | LB53 | CB287 | CB299 | RB13 | RB29 | CB863 | CB136 | RB729 | RB740 | RB96 | CB801 | TPB48 | RB92 | RB28 | RB12 | RB100 | RB107 | CB783 | LEDB10 | RB632 | RB611 | RB594 | RB728 | RB739 | RB653 | RB434 | RB470 | RB506 | RB542 | CB856 | CB862 | RB624 | RB602 | RB643 | LB52 | CB176 | RB120 | CB263 | CB195 | RB117 | CB244 | RB681 | CB125 | CB135 | RB700 | RB577 | RB586 | RB675 | RB459 | RB495 | RB567 | RB725 | RB719 | RB433 | RB469 | RB541 | RB531 | RB505 | CB295 | CB311 | CB317 | RB95 | CB281 | CB855 | LB51 | RB691 | RB83 | RB91 | RB705 | RB711 | CB800 | RB105 | CB183 | CB861 | CB209 | RB80 | LEDB9 | RB111 | RB115 | LB50 | CB854 | CB860 | CB455 | CB441 | RB680 | RB699 | RB690 | RB704 | CB208 | CB320 | RB674 | RB458 | RB494 | RB530 | RB566 | RB718 | RB724 | CB564 | CB575 | TPB36 | RB710 | CB853 | CB859 | RB641 | LB49 | RB631 | RB651 | CB647 | RB661 | CB732 | RB564 | RB528 | TPB30 | CB951 | LEDB8 | CB379 | CB758 | RB457 | RB493 | RB529 | RB565 | CB402 | CB799 | RB456 | RB610 | CB716 | RB492 | CB286 | CB633 | RB623 | CB486 | CB774 | RB584 | RB593 | CB526 | RB601 | CB435 | RB671 | CB275 | CB652 | CB293 | CB141 | CB157 | CB167 | TPB45 | CB177 | RB113 | CB203 | RB119 | CB285 | CB577 | CB635 | CB551 | CB649 | CB434 | CB403 | CB499 | CB416 | CB274 | CB300 | CB773 | LB48 | CB852 | CB378 | LEDB7 | CB632 | CB470 | CB648 | CB396 | CB324 | CB436 | CB576 | CB858 | CB614 | CB397 | CB319 | CB131 | TPB46 | LEDB11 | RB640 | RB670 | RB660 | RB650 | CB634 | TPB27 | RB491 | RB527 | FB1 | FB2 | RB455 | CB377 | RB125 | RB563 | CB154 | CB130 | RB592 | RB600 | RB609 | RB583 | RB622 | CB253 | CB265 | CB280 | CB291 | CB308 | RB630 | CB28 | RB490 | RB526 | CB196 | RB108 | RB454 | CB375 | RB562 | CB214 | CB232 | CB247 | RB126 | CB282 | CB296 | CB312 | CB318 | CB746 | CB770 | CB664 | RB207 | CB374 | CB363 | UB6 | RB146 | CB631 | CB645 | CB906 | RB178 | CB429 | CB453 | RB185 | CB479 | CB367 | CB769 | TPB28 | CB395 | CB917 | CB525 | CB630 | CB644 | CB539 | CB556 | CB452 | CB469 | CB485 | CB326 | CB433 | CB389 | CB498 | CB510 | CB401 | CB524 | RB145 | CB625 | CB629 | CB613 | CB1 | CB451 | CB468 | CB484 | CB555 | CB583 | CB569 | CB592 | CB414 | PTCB1 | CB432 | CB450 | CB350 | LEDB2 | CB612 | CB624 | CB680 | CB768 | CB582 | CB910 | TPB26 | CB628 | CB480 | CB591 | CB523 | CB638 | CB437 | CB651 | CB904 | RB194 | CB472 | CB650 | CB623 | CB611 | CB376 | CB682 | CB39 | CB31 | CB590 | CB454 | CB478 | CB637 | CB35 | CB756 | CB653 | RB156 | CB636 | CB325 | CB574 | CB543 | CB554 | CB568 | CB610 | CB622 | CB544 | CB483 | CB497 | CB775 | TPB35 | CB918 | CB36 | CB589 | CB581 | RB195 | CB911 | CB542 | CB553 | CB609 | CB621 | CB627 | CB567 | RB180 | CB496 | CB482 | RB179 | CB30 | CB380 | CB415 | CB449 | RB98 | CB467 | CB139 | RB101 | RB112 | CB202 | CB221 | CB1062 | CB1061 | CB580 | TPB39 | CB541 | LEDB1 | CB620 | CB481 | CB495 | CB166 | CB186 | CB201 | RB118 | CB431 | CB566 | RB153 | RB158 | CB316 | CB273 | CB294 | CB540 | CB639 | CB643 | CB619 | CB626 | CB310 | CB665 | RB208 | CB156 | CB430 | CB448 | CB466 | RB122 | CB254 | CB565 | RB175 | CB421 | RB332 | CB552 | PTCB2 | HSB1 | RB124 | RB193 | LB64 | LB63 | LB62 | LB69 | LB68 | LB67 | CB914 | UB9 | CB903 | RB322 | TPB7 | CB327 | RB321 | RB320 | CB921 | CB931 | CB923 | LB78 | RB319 | LB77 | RB318 | CB930 | L99 | RB334 | LB71 | R1071 | C779 | CB916 | RB333 | LB76 | R1072 | LB70 | R1037 | CB915 | R1073 | C781 | L97 | RB336 | CB913 | R1074 | R1043 | RB335 | CB912 | C783 | R1075 | LB75 | L98 | LB66 | R1076 | LB74 | LB65 | R1077 | C785 | L95 | R1070 | LB73 | R1078 | CB929 | CB997 | CB1031 | CB928 | CB937 | CB998 | CB927 | CB1020 | C542 | C548 | CB926 | CB994 | CB1032 | TP49 | CB1028 | CB1010 | DB2 | CB1026 | FB5 | RB758 | CB1017 | R1112 | CB1018 | CB1034 | R1120 | CB1086 | CB1084 | LB61 | R1092 | RB317 | RB277 | LB60 | RB276 | R1124 | RB316 | FB4 | DB1 | CB33 | LB59 | CB1087 | RB315 | LB58 | CB1048 | RB314 | CB1090 | RB1218 | CB1089 | R1131 | CB1052 | CB563 | R944 | R1128 | RB1220 | CB1053 | R1129 | CB760 | RB220 | CB1051 | R943 | CB764 | RB219 | R843 | CB763 | RB222 | R842 | CB562 | CB739 | RB649 | RB221 | RB709 | CB993 | CB561 | C518 | CB941 | UB15 | RB253 | RB726 | CB797 | CB579 | RB270 | CB1081 | RB252 | CB792 | CB966 | CB781 | RB269 | CB1067 | CB762 | RB251 | RB307 | RB297 | LB28 | CB965 | CB780 | RB1203 | RB268 | RB250 | CB1068 | CB761 | RB296 | RB306 | RB1204 | CB779 | LB27 | CB964 | RB267 | RB1205 | RB249 | CB1074 | RB295 | UB8 | RB305 | CB963 | RB248 | R1162 | RB144 | R1163 | RB304 | RB294 | RB143 | R1232 | R1122 | LB88 | RB142 | CB969 | RB749 | CB1045 | RB303 | RB141 | RB293 | CB681 | CB948 | RB191 | RB1214 | CB778 | CB924 | R1093 | RB140 | CB782 | CB672 | R1094 | CB791 | RB139 | CB947 | RB292 | RB302 | R1095 | RB200 | CB946 | RB291 | RB199 | RB138 | CB671 | CB967 | CB955 | CB670 | CB945 | CB968 | CB944 | RB198 | LB87 | CB943 | RB137 | CB933 | RB275 | LB86 | CB669 | RB136 | RB266 | RB247 | CB932 | CB784 | RB274 | CB883 | CB709 | RB265 | RB412 | RB246 | RB585 | RB279 | RB206 | CONNB6 | RB264 | RB245 | RB263 | CB777 | RB384 | CB822 | RB205 | RB262 | RB383 | RB411 | FB11 | RB621 | RB204 | RB410 | CB936 | RB382 | CB20 | LB47 | RB210 | RB240 | RB381 | LB46 | RB239 | CB23 | RB620 | RB409 | RB684 | RB238 | QB9 | CB22 | CB821 | RB237 | RB213 | RB212 | CB117 | CONNB5 | RB408 | RB380 | CB107 | CB19 | RB407 | QB8 | CB18 | RB379 | FB10 | RB84 | CB17 | RB88 | CB16 | RB406 | RB130 | RB133 | RB378 | CB93 | LB45 | RB129 | RB132 | RB377 | RB617 | CB220 | RB35 | RB405 | CB494 | CB796 | RB34 | LB44 | CB150 | CB216 | CB15 | CB149 | RB33 | CB820 | RB131 | RB687 | CB148 | CONNB4 | RB404 | CB174 | CB192 | RB32 | RB604 | CB191 | CB819 | RB31 | RB376 | RB30 | CB190 | RB403 | RB375 | CB112 | LB43 | CB204 | RB402 | FB9 | CB106 | RB374 | CB187 | CB145 | CB27 | LB42 | RB373 | CB1092 | CB144 | CB116 | CB165 | CB143 | CB115 | CB818 | CB164 | RB401 | CB142 | CB817 | RB432 | CONNB3 | RB431 | FB8 | LB41 | RB372 | CB712 | LB40 | RB371 | RB619 | CB816 | CB45 | RB370 | CB789 | RB369 | CB114 | RB618 | RB27 | RB11 | CB155 | RB168 | CB788 | RB10 | CB815 | RB167 | RB430 | CB162 | RB429 | CB787 | CB104 | CB140 | LB39 | RB26 | RB9 | CB439 | CB92 | CB786 | CB113 | RB25 | LB38 | CB438 | CB161 | CB957 | CB153 | CB814 | RB428 | RB235 | CB790 | CB972 | CB956 | CB44 | RB368 | CB138 | RB427 | RB1 | RB367 | CB51 | RB366 | RB668 | CB813 | RB365 | RB667 | LB37 | CB962 | CB974 | RB426 | RB425 | CB838 | LB82 | LB14 | LB36 | RB424 | RB423 | RB364 | CB812 | CB307 | RB363 | CB306 | CB91 | RB362 | LB7 | CB305 | LB9 | CB40 | LB19 | CB95 | RB361 | CB304 | CB373 | CB94 | RB642 | CB250 | CB340 | RB422 | CB372 | CB100 | CB249 | CB251 | RB421 | LB84 | CB303 | LB10 | CB133 | CB811 | CB371 | LB83 | CB708 | CB132 | CB248 | CB362 | CB99 | CB339 | CB707 | CB302 | CONNB2 | CB487 | RB400 | RB174 | CB301 | RB187 | CB98 | CB338 | LB35 | LB18 | RB360 | CB408 | LB34 | CB309 | CB361 | RB399 | RB359 | CB255 | LB17 | CB810 | RB398 | CB168 | CB360 | QB1 | CB37 | RB358 | LB13 | CB289 | CB809 | RB41 | RB357 | CB88 | CB298 | RB397 | LB21 | LB33 | RB20 | LB20 | RB19 | CB180 | TPB38 | LB32 | CB776 | C412 | CB731 | CB808 | RB356 | RB396 | R538 | RB355 | R521 | RB214 | RB395 | RB354 | CB807 | RB227 | RB353 | CB152 | CB172 | CB193 | CB233 | RB394 | LB31 | CB160 | CB185 | CB217 | CB986 | CB50 | LB25 | RB393 | CB269 | LB30 | CB49 | CB333 | RB104 | CB270 | LB4 | LB8 | CB6 | CB234 | CB26 | CB48 | CB806 | CB332 | CB10 | RB392 | CB25 | CB47 | CB181 | CB159 | RB202 | CB43 | RB352 | CB331 | CB987 | CB337 | CB572 | RB190 | RB154 | RB79 | RB391 | CB336 | CB288 | CB261 | RB78 | RB351 | CB335 | CB260 | RB77 | CB3 | RB350 | RB128 | CB348 | CB527 | CB71 | CB229 | RB76 | RB349 | LB1 | RB192 | CB76 | CB381 | CB2 | CB124 | CB578 | RB162 | CB388 | CB268 | CB297 | CB422 | CB134 | RB390 | CB246 | CB278 | RB75 | CB477 | CB407 | RB389 | CB75 | RB74 | CB406 | CB476 | RB73 | CB213 | CB684 | CB705 | CB475 | CB405 | RB72 | CB751 | RB692 | CB218 | RB388 | RB3 | RB71 | CB735 | CB766 | CB347 | CB8 | CB588 | CB713 | CB46 | RB2 | CB704 | CB720 | CB750 | RB348 | CB42 | CB7 | RB387 | CB692 | CB727 | RB45 | CB447 | CB122 | RB347 | CB723 | CB695 | CB738 | CB749 | RB346 | CB228 | CB267 | CB691 | CB714 | RB70 | C366 | CB266 | RB121 | CB70 | RB69 | CB197 | RB345 | C367 | RB68 | CB69 | CB258 | C368 | RB86 | CB68 | CB829 | CB446 | C369 | CB346 | CB67 | RB386 | CB445 | RB385 | CB66 | CB444 | CB65 | CB443 | CB587 | CB74 | UB13 | CB182 | CB206 | CB235 | CB73 | RB420 | CB980 | CB78 | CB257 | CB284 | RB67 | RB734 | RB344 | CB77 | CB271 | RB66 | RB733 | RB343 | RB419 | CB262 | CB87 | RB82 | CB979 | CB828 | CB86 | RB81 | RB342 | CB511 | CB85 | RB732 | CB528 | RB341 | CB84 | RB65 | CB230 | CB83 | RB64 | CB231 | CB978 | CB82 | RB63 | CB977 | RB62 | CB607 | RB418 | RB182 | CB976 | CB586 | RB61 | RB417 | RB60 | RB723 | CB81 | RB722 | CB685 | CB706 | RB698 | CB80 | CB608 | CB984 | RB715 | RB696 | CB79 | CB617 | RB717 | RB738 | CB243 | RB127 | CB358 | RB340 | CB242 | CB277 | CB387 | CB827 | RB416 | CB602 | CB493 | CB983 | CB241 | CB276 | RB339 | CB593 | RB415 | RB338 | CB537 | CB359 | RB337 | CB175 | CB411 | CB679 | CB752 | CB199 | CB971 | CB961 | CB227 | CB370 | RB716 | CB173 | CB198 | RB695 | RB737 | CB226 | RB414 | CB606 | CB772 | CB970 | CB960 | CB982 | RB413 | CB357 | CB393 | RB736 | TPB44 | CB690 | CB729 | CB410 | CB678 | CB748 | RB735 | RB103 | CB342 | CB981 | CB356 | CB659 | CB771 | CB392 | CB341 | TPB41 | CB726 | CB409 | CB655 | CB703 | CB689 | CB747 | CB38 | CB352 | CB722 | CB119 | CB391 | CB118 | CB501 | CB536 | CB677 | RB59 | CB725 | RB331 | CB573 | CB660 | TPB43 | CB616 | CB702 | CB745 | RB330 | RB196 | CB508 | RB58 | CB615 | TPB42 | CB688 | CB728 | CB744 | RB57 | CB507 | CB605 | CB427 | CB365 | RB56 | CB506 | RB313 | CB386 | RB55 | CB355 | CB901 | CB724 | CB701 | RB54 | CB549 | CB919 | CB344 | RB312 | RB53 | CB558 | CB64 | CB535 | CB343 | CB900 | CB694 | CB715 | CB743 | CB426 | RB311 | RB236 | CB369 | CB505 | CB534 | CB63 | CB474 | CB399 | CB700 | CB719 | CB504 | CB533 | RB18 | CB62 | CB473 | CB532 | CB560 | CB503 | CB61 | RB17 | CB492 | CB531 | CB742 | CB718 | CB385 | CB559 | CB909 | CB458 | RB16 | CB420 | CB60 | CB646 | CB683 | CB1060 | CB491 | CB538 | CB398 | CB767 | RB329 | RB15 | CB457 | CB59 | CB412 | CB658 | CB1059 | CB699 | CB741 | CB390 | CB717 | CB354 | CB418 | RB328 | CB58 | CB657 | CB502 | CB530 | CB471 | TPB31 | CB442 | TPB29 | CB640 | CB548 | CB419 | CB57 | CB595 | CB547 | CB698 | CB740 | CB394 | CB56 | CB353 | CB546 | CB674 | CB384 | RB148 | CB55 | CB697 | CB721 | CB13 | CB364 | CB521 | CB465 | RB147 | CB54 | CB425 | CB520 | RB327 | CB464 | CB557 | CB905 | RB326 | CB519 | CB663 | CB424 | CB598 | CB673 | CB693 | CB463 | CB53 | CB734 | CB902 | CB908 | CB518 | CB604 | CB4 | RB209 | CB12 | CB597 | CB765 | CB603 | TPB40 | CB517 | CB52 | RB52 | CB345 | CB656 | CB596 | TPB37 | RB197 | RB51 | CB516 | CB676 | RB310 | CB423 | RB50 | CB515 | CB675 | CB642 | CB662 | RB150 | TPB34 | CB462 | UB5 | RB309 | RB49 | CB514 | CB641 | CB661 | CB667 | CB461 | RB48 | CB513 | CB460 | CB666 | CB488 | RB308 | CB512 | CB920 | CB459 | CB24 | CB585 | CB490 | CB899 | CB601 | CB1091 | CB489 | RB172 | CB600 | TPB33 | RB323 | RB171 | CB599 | TPB32 | CB907 | CB571 | RB114 | RB106 | RB177 | CB529 | Excess check:Jan 19 15:43:21 2018 | PadStack_Check:Jan 19 14:44:25 2018 | XY-Check rotation:Jan 19 12:11:55 2018 | XY-Check txt overlap:Jan 19 13:55:54 2018 | XY-Etch cross-G11-S12:Jan 19 15:28:04 2018 | XY-Etch cross-G13-S14:Jan 19 15:28:04 2018 | XY-Etch cross-G15-S16:Jan 19 15:28:05 2018 | XY-Etch cross-G17-V18:Jan 19 15:28:06 2018 | XY-Etch cross-G19-BOTTOM:Jan 19 15:28:10 2018 | XY-Etch cross-S5-G6:Jan 19 15:26:52 2018 | XY-Etch cross-S7-G8:Jan 19 15:27:11 2018 | XY-Etch cross-S9-G10:Jan 19 15:27:40 2018 | XY-Etch cross-TOP-G2:Jan 19 15:26:17 2018 | XY-Etch cross-V3-G4:Jan 19 15:26:49 2018 | XY-Excess check:Jan 19 15:43:21 2018 | XY-Mask check:Jan 19 15:15:20 2018 | XY-Norefdes:Jan 19 12:12:04 2018 | XY-PadStack_Check:Jan 19 14:44:25 2018 | XY-Symbol compare:Dec 22 19:50:56 2017 | XY-bbvia check:Jan 19 15:43:02 2018 | XY-shape min check:Jan 19 14:44:36 2018 | bbvia check:Jan 19 15:43:02 2018 | check acute:Jan 15 12:54:48 2018 | check cline width:Jan 09 15:45:23 2018 | check rotation:Jan 19 12:11:55 2018 | check txt overlap:Jan 19 13:55:54 2018 | check txt:Jan 13 11:21:42 2018 | create nettxt:Jan 04 17:24:08 2018 | create plane:Jan 04 17:24:25 2018 | dxf to pin check:Jan 09 14:53:49 2018 | etch cross-G11-S12:Jan 19 15:28:04 2018 | etch cross-G13-S14:Jan 19 15:28:04 2018 | etch cross-G15-S16:Jan 19 15:28:05 2018 | etch cross-G17-V18:Jan 19 15:28:06 2018 | etch cross-G19-BOTTOM:Jan 19 15:28:10 2018 | etch cross-S5-G6:Jan 19 15:26:52 2018 | etch cross-S7-G8:Jan 19 15:27:11 2018 | etch cross-S9-G10:Jan 19 15:27:40 2018 | etch cross-TOP-G2:Jan 19 15:26:17 2018 | etch cross-V3-G4:Jan 19 15:26:49 2018 | norefdes:Jan 19 12:12:04 2018 | outline check:Jan 09 15:48:30 2018 | prop check:Jan 09 15:23:12 2018 | shape min check:Jan 19 14:44:36 2018 | symbol compare:Dec 22 19:50:56 2017 | G19 (GND_LAYER_19)                         19 | G8 (GND_LAYER_8)                           8 | G10 (GND_LAYER_10)                     10 | S9 (SIGNAL_LAYER_9)                    9 | NO MUST CUT LAYER:S7 | MUST CUT LAYER:G6 | NO MUST CUT LAYER:S16 | MUST CUT LAYER:G15 | BACKDRILL(DRILL-BD-20-12)                    36 | BACKDRILL(DRILL-BD-1-15                    35 | NO MUST CUT LAYER:S9 | MUST CUT LAYER:G8 | BACKDRILL(DRILL-BD-1-8)                   31 | BACKDRILL(DRILL-BD-1-6)                    34 | BACKDRILL(DRILL-BD-1-4)                    35 | NO MUST CUT LAYER:G11 | NO MUST CUT LAYER:S5 | MUST CUT LAYER:S12 | MUST CUT LAYER:G4 | NOTES: | - DRILL SIZES LISTED IN LEGEND | ARE CONSIDERED FINISHED. | - VENDOR IS REQUIRED TO SELECT | TOOLING FOR OVERDRILLING. | - LEGEND DOES NOT SPECIFY DEPTH | INTO ADJACENT DIELECTRIC LAYER. | FIGURE | SIZE | 10.0 | 8.0 | 14.6 | 12.0 | 22.0 | 31.5 | 37.0 | 40.0 | 41.3 | 41.34 | 47.0 | 63.0 | 71.0 | 166.0 | 32.0 | 36.0 | 44.0 | 98.0 | 118.0 | 128.0 | 138.0 | 177.0 | 100.0x40.0 | BACKDRILL: TOP to G15 | ALL UNITS ARE IN MILS | BACKDRILL: BOTTOM to G8 | BACKDRILL: TOP to G6 | TOLERANCE | +3.0/-3.0 | DRILL CHART: TOP to BOTTOM | BACKDRILL: BOTTOM to G13 | BACKDRILL: BOTTOM to G15 | BACKDRILL: BOTTOM to G10 | BACKDRILL: TOP to G8 | +2.0/-2.0 | BACKDRILL: BOTTOM to G17 | PLATED | NON-PLATED | QTY | 18 | 2539 | 675 | 6412 | 556 | 207 | 4 | 48 | 24 | 10 | 12 | 29 | 21 | 34 | 42 | 40 | 16
